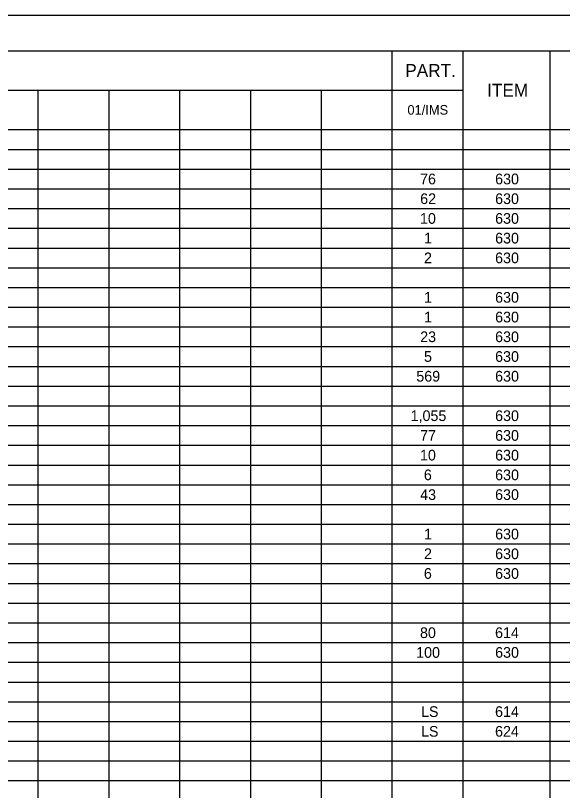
# Model space of a CAD drawing. Extents: x 0 to 34, y 0 to 22.
# Drawn here: x 9.22 to 16.98, y 11 to 22 of the extents above; entities that cross this region are included whole.
import ezdxf

# ---------------------------------------------------------------- set-up
doc = ezdxf.new("R2010")
doc.units = 0
for name, color, linetype in [('SH_Border', 7, 'Continuous'), ('SH_Cut_Line', 7, 'Continuous'), ('SH_Text', 7, 'Continuous')]:
    doc.layers.add(name, color=color, linetype=linetype)

msp = doc.modelspace()

# ---------------------------------------------------------------- linework, layer by layer
at = {"layer": 'SH_Border'}
msp.add_lwpolyline([(1.5, 21.5), (33.5, 21.5), (33.5, 0.5), (1.5, 0.5)], close=True, dxfattribs=at)
at = {"layer": 'SH_Cut_Line'}
msp.add_lwpolyline([(0, 0), (34, 0), (34, 22), (0, 22)], close=True, dxfattribs=at)
at = {"layer": 'SH_Text'}
for p, q in [((1.5, 21.5), (32.004, 21.5)), ((14.561, 21.5), (14.561, 0.5)), ((15.566, 21.5), (15.566, 0.5)), ((16.801, 21.5), (16.801, 0.5)), ((1.5, 20.94), (15.566, 20.94)), ((9.538, 20.94), (9.538, 0.5)), ((10.542, 20.94), (10.542, 0.5)), ((11.547, 20.94), (11.547, 0.5)), ((12.552, 20.94), (12.552, 0.5)), ((13.556, 20.94), (13.556, 0.5)), ((1.5, 20.38), (32.004, 20.38)), ((1.5, 20.1), (32.004, 20.1)), ((1.5, 19.82), (32.004, 19.82)), ((1.5, 19.54), (32.004, 19.54)), ((1.5, 19.26), (32.004, 19.26)), ((1.5, 18.98), (32.004, 18.98)), ((1.5, 18.7), (32.004, 18.7)), ((1.5, 18.42), (32.004, 18.42)), ((1.5, 18.14), (32.004, 18.14)), ((1.5, 17.86), (32.004, 17.86)), ((1.5, 17.58), (32.004, 17.58)), ((1.5, 17.3), (32.004, 17.3)), ((1.5, 17.02), (32.004, 17.02)), ((1.5, 16.74), (32.004, 16.74)), ((1.5, 16.46), (32.004, 16.46)), ((1.5, 16.18), (32.004, 16.18)), ((1.5, 15.9), (32.004, 15.9)), ((1.5, 15.62), (32.004, 15.62)), ((1.5, 15.34), (32.004, 15.34)), ((1.5, 15.06), (32.004, 15.06)), ((1.5, 14.78), (32.004, 14.78)), ((1.5, 14.5), (32.004, 14.5)), ((1.5, 14.22), (32.004, 14.22)), ((1.5, 13.94), (32.004, 13.94)), ((1.5, 13.66), (32.004, 13.66)), ((1.5, 13.38), (32.004, 13.38)), ((1.5, 13.1), (32.004, 13.1)), ((1.5, 12.82), (32.004, 12.82)), ((1.5, 12.54), (32.004, 12.54)), ((1.5, 12.26), (32.004, 12.26)), ((1.5, 11.98), (32.004, 11.98)), ((1.5, 11.7), (32.004, 11.7)), ((1.5, 11.42), (32.004, 11.42)), ((1.5, 11.14), (32.004, 11.14))]:
    msp.add_line(p, q, dxfattribs=at)

# ---------------------------------------------------------------- texts
for s, height, p in [('PART.', 0.1818, (14.75, 21.129)), ('ITEM', 0.1818, (15.912, 20.849)), ('01/IMS', 0.1364, (14.78, 20.592)), ('76', 0.1515, (14.959, 19.604)), ('630', 0.1515, (16.024, 19.604)), ('62', 0.1515, (14.961, 19.324)), ('630', 0.1515, (16.024, 19.324)), ('10', 0.1515, (14.958, 19.044)), ('630', 0.1515, (16.024, 19.044)), ('1', 0.152, (15.015, 18.764)), ('630', 0.1515, (16.024, 18.764)), ('2', 0.152, (15.015, 18.484)), ('630', 0.1515, (16.024, 18.484)), ('1', 0.152, (15.015, 17.924)), ('630', 0.1515, (16.024, 17.924)), ('1', 0.152, (15.015, 17.644)), ('630', 0.1515, (16.024, 17.644)), ('23', 0.1515, (14.961, 17.364)), ('630', 0.1515, (16.024, 17.364)), ('5', 0.152, (15.015, 17.084)), ('630', 0.1515, (16.024, 17.084)), ('569', 0.1515, (14.906, 16.804)), ('630', 0.1515, (16.024, 16.804)), ('1,055', 0.1515, (14.825, 16.244)), ('630', 0.1515, (16.024, 16.244)), ('77', 0.1515, (14.96, 15.964)), ('630', 0.1515, (16.024, 15.964)), ('10', 0.1515, (14.958, 15.684)), ('630', 0.1515, (16.024, 15.684)), ('6', 0.152, (15.013, 15.404)), ('630', 0.1515, (16.024, 15.404)), ('43', 0.1515, (14.961, 15.124)), ('630', 0.1515, (16.024, 15.124)), ('1', 0.152, (15.015, 14.564)), ('630', 0.1515, (16.024, 14.564)), ('2', 0.152, (15.015, 14.284)), ('630', 0.1515, (16.024, 14.284)), ('6', 0.152, (15.013, 14.004)), ('630', 0.1515, (16.024, 14.004)), ('80', 0.1515, (14.958, 13.164)), ('614', 0.1515, (16.023, 13.164)), ('100', 0.1515, (14.904, 12.884)), ('630', 0.1515, (16.024, 12.884)), ('LS', 0.1515, (14.973, 12.044)), ('614', 0.1515, (16.023, 12.044)), ('LS', 0.1515, (14.973, 11.764)), ('624', 0.1515, (16.023, 11.764))]:
    msp.add_text(s, height=height, dxfattribs=at).set_placement(p)

doc.saveas('drawing.dxf')
